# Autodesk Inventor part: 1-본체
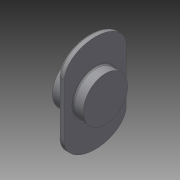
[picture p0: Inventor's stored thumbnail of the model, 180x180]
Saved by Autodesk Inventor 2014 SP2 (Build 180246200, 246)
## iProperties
Created: 2015-02
Part Number: 1-본체
Material: 일반
Document SubType Name: Modeling
Designer: 201-09
Density: 1 g/cm^3
Appearance: 기본값
Author: 201-09
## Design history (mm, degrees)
sketch "스케치1"
  geometry: L1 (70, -60)-(70, 60); L2 (-70, 60)-(-70, -60); L3 (-70, -60)-(70, 60); L4 (70, -60)-(-70, 60); L5 (0, 110)-(0, 0); L6 (0, -110)-(0, 0); 2 further points; 2 other entities
  constraints: 12 end point, 2 midpoint, 2 point on line, 2 vertical, 1 parallel, 10 other
  dimensions: "d1" = 140 distance between parallel lines of L1 L2; "d5" = 50 distance of point (0, 60) L5.start; "d6" = 50 distance of point (0, -60) L6.start; "d7" = 120 distance of point (0, -60) point (0, 60); "d8" = 220 distance of L6.start L5.start; "d9" = 140 horizontal distance of L1.start L2.start; "d10" = 120 vertical distance of L2.end L1.end; "d11" = 110 distance of L5.start L5.end; "d12" = 120 vertical distance of L1.start L2.start
extrude "돌출1" new body sketch "스케치1" distance "d13" = 12; taper "d14" = 0 deg
fillet "모깎기1" dims "d15" = 3
node "작업 평면1"
sketch "스케치2"
  geometry: C1 r 50 at (0, 0); 1 further point
  constraints: 1 centre point, 1 coincident
  dimensions: "d17" = 100 diameter of C1
extrude "돌출2" join sketch "스케치2" distance "d18" = 70; taper "d19" = 0 deg
fillet "모깎기2" dims "d20" = 3
node "작업 평면2"
sketch "스케치3"
  geometry: L1 (-60, -70)-(60, -70) reference; L2 (60, 70)-(-60, 70) reference; L3 (60, -53)-(-60, -53); L4 (-60, 53)-(60, 53); L5 (93, 0)-(0, 0); C1 r 10 at (93, 0); 1 further point
  constraints: 6 end point, 4 parallel, 3 vertical alignment, 1 centre point, 1 coincident, 6 other
  dimensions: "d22" = 10 radius of C1; "d23" = 17 distance between parallel lines of L1 L3; "d24" = 93 distance of L5.start L5.end; "d25" = 53 distance between parallel lines of L3 L5
extrude "돌출3" join sketch "스케치3" stored distance "d26" = 70; taper "d27" = 0 deg
node "솔리드1"
other parameters: "d16" = 23, "d21" = 5
